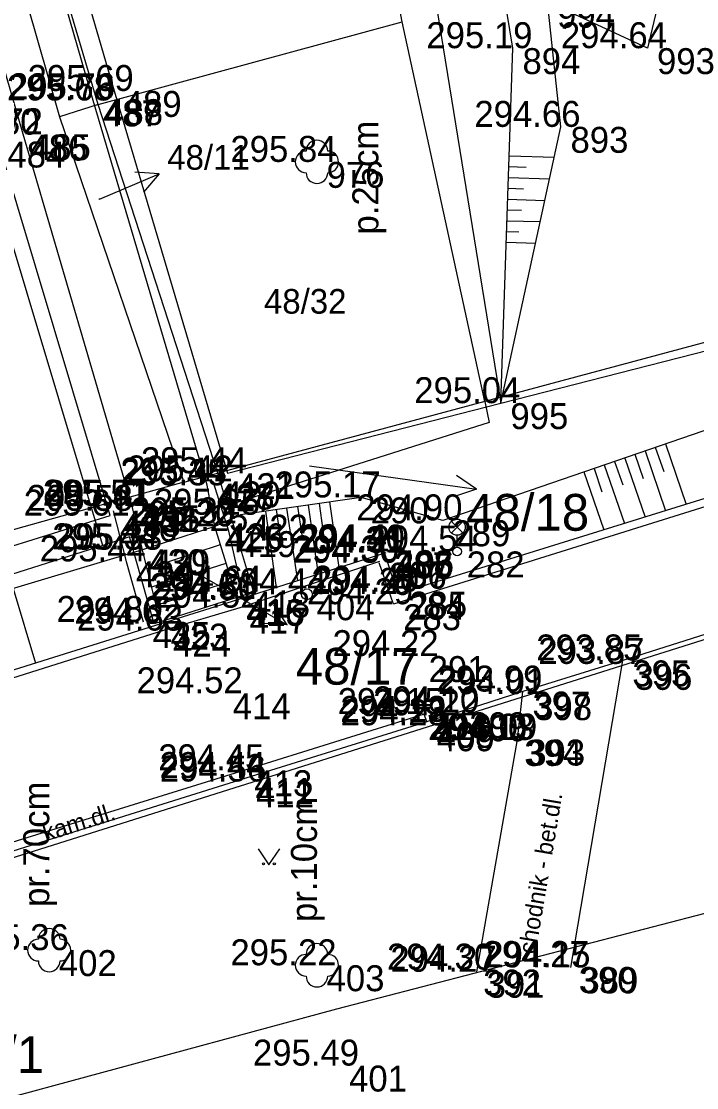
# Model space of a CAD drawing. Extents: x -599970 to -599524, y -1154772 to -1154457.
# Drawn here: x -599781.27 to -599765.66, y -1154687.91 to -1154663.25 of the extents above; entities that cross this region are included whole.
import ezdxf

# ---------------------------------------------------------------- set-up
doc = ezdxf.new("R2010")
doc.units = 0
for name, color, linetype in [('Z-ELEKTRICKE SKRINE LAMPY', 7, 'Continuous'), ('Z-KATASTRALNI MAPA', 7, 'Continuous'), ('Z-PLOT DRATENY', 7, 'Continuous'), ('Z-PLOT DREVENY', 7, 'Continuous'), ('Z-PLYNOVODNI SOUPATA HUP', 7, 'Continuous'), ('Z-PODROBNE BODY', 7, 'Continuous'), ('Z-PODROBNE BODY-CISLO', 7, 'Continuous'), ('Z-PODROBNE BODY-VYSKA', 7, 'Continuous'), ('Z-POPISY OBJEKTU A ZPEVNENYCH PLOCH', 7, 'Continuous'), ('Z-PRUMERY KMENU STROMU', 7, 'Continuous'), ('Z-SCHODY', 7, 'Continuous'), ('Z-SRAFOVANI SVAHU', 7, 'Continuous'), ('Z-STROMY ZNACKY KULTUR', 7, 'Continuous'), ('Z-TERENNI HRANY PATY', 7, 'Continuous'), ('Z-ZABRADLI', 7, 'Continuous'), ('Z-ZPEVNENE PLOCHY', 7, 'Continuous')]:
    doc.layers.add(name, color=color, linetype=linetype)

msp = doc.modelspace()

# ---------------------------------------------------------------- linework, layer by layer
at = {"layer": 'Z-ELEKTRICKE SKRINE LAMPY'}
for p, q in [((-599771.332, -1154675.079), (-599771.068, -1154674.815)), ((-599771.064, -1154675.078), (-599771.328, -1154674.813)), ((-599771.2, -1154675.41), (-599771.2, -1154675.135))]:
    msp.add_line(p, q, dxfattribs=at)
for centre, radius in [((-599771.2, -1154674.948), 0.188), ((-599771.2, -1154675.51), 0.1)]:
    msp.add_circle(centre, radius, dxfattribs=at)
at = {"layer": 'Z-KATASTRALNI MAPA'}
for p, q in [((-599772.47, -1154663.26), (-599776.02, -1154644.14)), ((-599779.5, -1154665.17), (-599784.88, -1154646.97)), ((-599725.18, -1154659.85), (-599770.56, -1154672.04)), ((-599779.5, -1154665.17), (-599772.47, -1154663.26)), ((-599770.56, -1154672.04), (-599772.47, -1154663.26)), ((-599779.5, -1154665.17), (-599780.39, -1154665.46)), ((-599776.73, -1154673.7), (-599779.5, -1154665.17)), ((-599780.39, -1154665.46), (-599777.52, -1154673.91)), ((-599779.47, -1154667.36), (-599778.089, -1154666.774)), ((-599778.089, -1154666.774), (-599778.647, -1154666.739)), ((-599778.089, -1154666.774), (-599778.452, -1154667.2)), ((-599779.47, -1154667.36), (-599779.48, -1154667.36)), ((-599770.56, -1154672.04), (-599776.73, -1154673.7)), ((-599777.52, -1154673.91), (-599776.73, -1154673.7)), ((-599776.51, -1154674.45), (-599776.73, -1154673.7)), ((-599774.61, -1154673.53), (-599772.24, -1154673.86)), ((-599777.52, -1154673.91), (-599779.65, -1154674.5)), ((-599772.24, -1154673.86), (-599770.754, -1154674.069)), ((-599770.754, -1154674.069), (-599771.215, -1154673.751)), ((-599770.754, -1154674.069), (-599771.285, -1154674.247)), ((-599779.39, -1154675.37), (-599779.65, -1154674.5)), ((-599779.39, -1154675.37), (-599848.12, -1154697.2)), ((-599777.73, -1154675.72), (-599776.43, -1154676.46)), ((-599776.43, -1154676.46), (-599775.13, -1154677.21)), ((-599775.13, -1154677.21), (-599775.439, -1154676.743)), ((-599775.13, -1154677.21), (-599775.689, -1154677.177))]:
    msp.add_line(p, q, dxfattribs=at)
for points in [[(-599779.65, -1154674.5), (-599784.9, -1154657), (-599786.85, -1154655.89), (-599787.57, -1154653.53), (-599785.79, -1154652.94), (-599792.35, -1154631.92), (-599798.2, -1154633.66), (-599805.39, -1154642.63)], [(-599784.88, -1154646.97), (-599785.65, -1154647.16), (-599780.39, -1154665.46)], [(-599834.98, -1154699.48), (-599751.66, -1154673.18), (-599740.79, -1154669.9), (-599738.46, -1154669.48), (-599735.86, -1154669.61), (-599733.7, -1154670.53), (-599731.62, -1154671.85), (-599729.9, -1154673.34)], [(-599770.56, -1154672.04), (-599770.46, -1154672.53), (-599776.51, -1154674.45)], [(-599776.51, -1154674.45), (-599775.91, -1154676.45), (-599778.2, -1154677.18), (-599778.77, -1154675.17), (-599779.39, -1154675.37)], [(-599779.65, -1154674.5), (-599852.06, -1154694.84), (-599855.48, -1154695.93)], [(-599783.66, -1154688.71), (-599773.98, -1154686.09), (-599748.46, -1154679.46)]]:
    msp.add_lwpolyline(points, dxfattribs=at)
at = {"layer": 'Z-PLOT DRATENY'}
for points in [[(-599780.14, -1154619.26), (-599779.06, -1154624.05), (-599777.14, -1154634.68), (-599775.65, -1154643.75), (-599773.83, -1154653.48), (-599771.85, -1154661.81), (-599770.19, -1154672.08)], [(-599790.59, -1154625.68), (-599789.41, -1154629.89), (-599785.15, -1154644.86), (-599782.34, -1154653.87), (-599779.13, -1154664.86), (-599776.51, -1154673.7), (-599770.19, -1154672.08), (-599762.65, -1154670.15), (-599753.18, -1154667.49), (-599743.82, -1154665.08), (-599731.66, -1154661.71), (-599725.96, -1154660.31)]]:
    msp.add_lwpolyline(points, dxfattribs=at)
at = {"layer": 'Z-PLOT DREVENY'}
for points in [[(-599779.22, -1154674.68), (-599781.82, -1154666.03), (-599784.68, -1154656.11), (-599785.66, -1154655.83), (-599787.35, -1154656.31)], [(-599812.56, -1154685.16), (-599801.32, -1154681.65), (-599791.39, -1154678.5), (-599786.35, -1154676.9), (-599779.22, -1154674.68)]]:
    msp.add_lwpolyline(points, dxfattribs=at)
at = {"layer": 'Z-PLYNOVODNI SOUPATA HUP'}
msp.add_circle((-599774.67, -1154676.5), 0.125, dxfattribs=at)
at = {"layer": 'Z-PODROBNE BODY'}
for p, q in [((-599769.91, -1154663.87), (-599769.91, -1154663.87)), ((-599766.8, -1154663.87), (-599766.8, -1154663.87)), ((-599779.61, -1154665.08), (-599779.61, -1154665.08)), ((-599779.56, -1154665.05), (-599779.56, -1154665.05)), ((-599779.13, -1154664.86), (-599779.13, -1154664.86)), ((-599768.8, -1154665.69), (-599768.8, -1154665.69)), ((-599781.23, -1154665.86), (-599781.23, -1154665.86)), ((-599774.44, -1154666.5), (-599774.44, -1154666.5)), ((-599770.19, -1154672.08), (-599770.19, -1154672.08)), ((-599776.51, -1154673.7), (-599776.51, -1154673.7)), ((-599776.98, -1154673.94), (-599776.98, -1154673.94)), ((-599776.84, -1154673.89), (-599776.84, -1154673.89)), ((-599776.98, -1154673.98), (-599776.98, -1154673.98)), ((-599778.78, -1154674.45), (-599778.78, -1154674.45)), ((-599778.71, -1154674.46), (-599778.71, -1154674.46)), ((-599773.42, -1154674.26), (-599773.42, -1154674.26)), ((-599779.22, -1154674.68), (-599779.22, -1154674.68)), ((-599779.15, -1154674.57), (-599779.15, -1154674.57)), ((-599776.21, -1154674.66), (-599776.21, -1154674.66)), ((-599776.8, -1154674.93), (-599776.8, -1154674.93)), ((-599776.74, -1154674.86), (-599776.74, -1154674.86)), ((-599771.53, -1154674.79), (-599771.53, -1154674.79)), ((-599776.48, -1154675.04), (-599776.48, -1154675.04)), ((-599778.56, -1154675.46), (-599778.56, -1154675.46)), ((-599778.47, -1154675.47), (-599778.47, -1154675.47)), ((-599772.88, -1154675.53), (-599772.88, -1154675.53)), ((-599772.86, -1154675.49), (-599772.86, -1154675.49)), ((-599772.85, -1154675.54), (-599772.85, -1154675.54)), ((-599772.83, -1154675.48), (-599772.83, -1154675.48)), ((-599771.2, -1154675.51), (-599771.2, -1154675.51)), ((-599778.85, -1154675.74), (-599778.85, -1154675.74)), ((-599773, -1154675.77), (-599773, -1154675.77)), ((-599772.99, -1154675.74), (-599772.99, -1154675.74)), ((-599776.16, -1154676.44), (-599776.16, -1154676.44)), ((-599772.53, -1154676.44), (-599772.53, -1154676.44)), ((-599776.3, -1154676.61), (-599776.3, -1154676.61)), ((-599776.28, -1154676.63), (-599776.28, -1154676.63)), ((-599774.67, -1154676.5), (-599774.67, -1154676.5)), ((-599772.57, -1154676.49), (-599772.57, -1154676.49)), ((-599776.22, -1154676.81), (-599776.22, -1154676.81)), ((-599772.67, -1154676.73), (-599772.67, -1154676.73)), ((-599778.46, -1154677.14), (-599778.46, -1154677.14)), ((-599778.05, -1154677.18), (-599778.05, -1154677.18)), ((-599777.99, -1154677.34), (-599777.99, -1154677.34)), ((-599772.08, -1154677.93), (-599772.08, -1154677.93)), ((-599767.37, -1154678.03), (-599767.37, -1154678.03)), ((-599767.32, -1154678.11), (-599767.32, -1154678.11)), ((-599776.61, -1154678.79), (-599776.61, -1154678.79)), ((-599769.68, -1154678.75), (-599769.68, -1154678.75)), ((-599769.64, -1154678.81), (-599769.64, -1154678.81)), ((-599771.96, -1154679.27), (-599771.96, -1154679.27)), ((-599771.14, -1154679.23), (-599771.14, -1154679.23)), ((-599771.14, -1154679.3), (-599771.14, -1154679.3)), ((-599771.9, -1154679.45), (-599771.9, -1154679.45)), ((-599771.89, -1154679.53), (-599771.89, -1154679.53)), ((-599769.87, -1154679.87), (-599769.87, -1154679.87)), ((-599769.8, -1154679.86), (-599769.8, -1154679.86)), ((-599776.11, -1154680.57), (-599776.11, -1154680.57)), ((-599776.08, -1154680.75), (-599776.08, -1154680.75)), ((-599776.07, -1154680.83), (-599776.07, -1154680.83)), ((-599780.63, -1154684.73), (-599780.63, -1154684.73)), ((-599774.44, -1154685.08), (-599774.44, -1154685.08)), ((-599770.82, -1154685.18), (-599770.82, -1154685.18)), ((-599770.74, -1154685.23), (-599770.74, -1154685.23)), ((-599768.61, -1154685.12), (-599768.61, -1154685.12)), ((-599768.57, -1154685.13), (-599768.57, -1154685.13)), ((-599773.92, -1154687.4), (-599773.92, -1154687.4))]:
    msp.add_line(p, q, dxfattribs=at)
at = {"layer": 'Z-SCHODY'}
for points in [[(-599776.28, -1154676.63), (-599776.8, -1154674.93), (-599778.47, -1154675.47)], [(-599778.36, -1154675.9), (-599776.67, -1154675.35)], [(-599778.05, -1154677.18), (-599778.47, -1154675.47)], [(-599778.26, -1154676.33), (-599776.54, -1154675.78)], [(-599778.15, -1154676.75), (-599776.41, -1154676.19)]]:
    msp.add_lwpolyline(points, dxfattribs=at)
at = {"layer": 'Z-SRAFOVANI SVAHU'}
for points in [[(-599769.99, -1154666.36), (-599768.95, -1154666.39)], [(-599770, -1154666.61), (-599769.6, -1154666.62)], [(-599770.01, -1154666.86), (-599769.06, -1154666.89)], [(-599770.02, -1154667.11), (-599769.66, -1154667.12)], [(-599770.03, -1154667.36), (-599769.17, -1154667.39)], [(-599770.04, -1154667.61), (-599769.71, -1154667.62)], [(-599770.05, -1154667.86), (-599769.28, -1154667.88)], [(-599770.05, -1154668.11), (-599769.77, -1154668.12)], [(-599770.06, -1154668.36), (-599769.38, -1154668.38)], [(-599766.85, -1154673.18), (-599766.38, -1154674.57)], [(-599766.62, -1154673.1), (-599766.42, -1154673.66)], [(-599766.38, -1154673.02), (-599765.9, -1154674.42)], [(-599767.56, -1154673.43), (-599767.37, -1154673.97)], [(-599767.32, -1154673.35), (-599766.85, -1154674.72)], [(-599767.09, -1154673.26), (-599766.9, -1154673.82)], [(-599768.27, -1154673.67), (-599767.81, -1154675.01)], [(-599768.03, -1154673.59), (-599767.85, -1154674.13)], [(-599767.8, -1154673.51), (-599767.33, -1154674.86)], [(-599774.64, -1154674.44), (-599774.41, -1154676.04)], [(-599774.39, -1154674.4), (-599774.3, -1154675.02)], [(-599774.15, -1154674.36), (-599773.93, -1154675.88)], [(-599775.63, -1154674.58), (-599775.38, -1154676.34)], [(-599775.38, -1154674.54), (-599775.28, -1154675.23)], [(-599775.14, -1154674.51), (-599774.89, -1154676.19)], [(-599774.89, -1154674.47), (-599774.79, -1154675.13)], [(-599781.46, -1154676.37), (-599780.95, -1154678.09)]]:
    msp.add_lwpolyline(points, dxfattribs=at)
at = {"layer": 'Z-STROMY ZNACKY KULTUR'}
msp.add_lwpolyline([(-599775.8, -1154682.385), (-599775.55, -1154682.76), (-599775.3, -1154682.385)], dxfattribs=at)
for centre, radius in [((-599774.44, -1154666.5), 0.00025), ((-599775.675, -1154682.735), 0.025), ((-599775.425, -1154682.735), 0.025), ((-599780.63, -1154684.73), 0.00025), ((-599774.44, -1154685.08), 0.00025)]:
    msp.add_circle(centre, radius, dxfattribs=at)
for centre, start, end in [((-599774.44, -1154666.25), 0, 180), ((-599774.69, -1154666.5), 90, 270), ((-599774.19, -1154666.5), 270, 90), ((-599774.44, -1154666.75), 180, 360), ((-599780.63, -1154684.48), 0, 180), ((-599780.88, -1154684.73), 90, 270), ((-599780.38, -1154684.73), 270, 90), ((-599774.44, -1154684.83), 0, 180), ((-599780.63, -1154684.98), 180, 360), ((-599774.69, -1154685.08), 90, 270), ((-599774.19, -1154685.08), 270, 90), ((-599774.44, -1154685.33), 180, 360)]:
    msp.add_arc(centre, 0.25, start, end, dxfattribs=at)
at = {"layer": 'Z-TERENNI HRANY PATY'}
for points in [[(-599770.19, -1154672.08), (-599768.8, -1154665.69), (-599769.11, -1154662.8), (-599769.78, -1154656.63), (-599767.23, -1154647.84), (-599766.21, -1154641.96), (-599766.49, -1154640.37)], [(-599770.19, -1154672.08), (-599769.91, -1154663.87), (-599771.22, -1154655.86), (-599770.65, -1154650.7), (-599770.95, -1154647.47), (-599768.69, -1154645.23)], [(-599742.26, -1154667.02), (-599744.49, -1154666.27), (-599753.03, -1154668.55), (-599762.24, -1154671.6), (-599771.53, -1154674.79), (-599773.42, -1154674.26), (-599776.21, -1154674.66), (-599776.8, -1154674.93)], [(-599778.47, -1154675.47), (-599786.05, -1154677.74), (-599791.05, -1154679.79), (-599801.02, -1154682.6), (-599812.13, -1154686.2)]]:
    msp.add_lwpolyline(points, dxfattribs=at)
at = {"layer": 'Z-ZABRADLI'}
for points in [[(-599776.16, -1154676.44), (-599776.48, -1154675.04), (-599776.84, -1154673.89)], [(-599779.15, -1154674.57), (-599778.85, -1154675.74), (-599778.46, -1154677.14)]]:
    msp.add_lwpolyline(points, dxfattribs=at)
at = {"layer": 'Z-ZPEVNENE PLOCHY'}
for points in [[(-599754.14, -1154621.91), (-599757.46, -1154625.05), (-599757.52, -1154625.29), (-599760.31, -1154636.94), (-599763.2, -1154648.7), (-599766.8, -1154663.87), (-599769.11, -1154662.8), (-599767.23, -1154647.84), (-599764.82, -1154638.47), (-599762.25, -1154627.96), (-599761.65, -1154625.43)], [(-599776.8, -1154674.93), (-599776.98, -1154673.98), (-599779.61, -1154665.08), (-599782.84, -1154653.93), (-599785.44, -1154645), (-599789.78, -1154630.07), (-599790.16, -1154628.81)], [(-599778.47, -1154675.47), (-599778.71, -1154674.46), (-599781.23, -1154665.86), (-599784.02, -1154656.22), (-599785.76, -1154654.87)], [(-599742.28, -1154666.02), (-599742.26, -1154667.02), (-599752.5, -1154670.22), (-599761.75, -1154673.13), (-599772.57, -1154676.49), (-599772.88, -1154675.53)], [(-599742.12, -1154666.17), (-599742.05, -1154667.12), (-599752.44, -1154670.39), (-599761.7, -1154673.3), (-599772.67, -1154676.73), (-599773, -1154675.77)], [(-599741.96, -1154670.11), (-599744.27, -1154670.81), (-599744.9, -1154671.03), (-599746.24, -1154671.41), (-599751.27, -1154672.97), (-599751.54, -1154673.05), (-599760.81, -1154675.95), (-599767.37, -1154678.03), (-599769.68, -1154678.75), (-599771.16, -1154679.23), (-599771.94, -1154679.46)], [(-599772.85, -1154675.54), (-599776.28, -1154676.63), (-599778.05, -1154677.18), (-599785.5, -1154679.52), (-599790.53, -1154681.1), (-599800.67, -1154684.32), (-599811.53, -1154687.77)], [(-599772.99, -1154675.74), (-599776.22, -1154676.81), (-599777.99, -1154677.34), (-599785.42, -1154679.68), (-599790.47, -1154681.24), (-599800.61, -1154684.48), (-599811.46, -1154687.9)], [(-599768.57, -1154685.13), (-599767.37, -1154678.03)], [(-599770.74, -1154685.23), (-599769.8, -1154679.86), (-599769.68, -1154678.75)], [(-599771.9, -1154679.45), (-599771.96, -1154679.27), (-599776.11, -1154680.57), (-599782.94, -1154682.69), (-599783.93, -1154682.97), (-599785.28, -1154683.4), (-599786.24, -1154683.72), (-599788.16, -1154684.29), (-599788.07, -1154684.53)], [(-599771.9, -1154679.45), (-599776.08, -1154680.75), (-599782.88, -1154682.88), (-599783.87, -1154683.12), (-599785.23, -1154683.58), (-599786.18, -1154683.89), (-599788.07, -1154684.53), (-599789.03, -1154684.79), (-599799.87, -1154688.27), (-599810.12, -1154691.54)]]:
    msp.add_lwpolyline(points, dxfattribs=at)

# ---------------------------------------------------------------- texts
at = {"layer": 'Z-KATASTRALNI MAPA'}
for s, height, p in [('48/11', 0.57, (-599777.9, -1154666.68)), ('48/32', 0.57, (-599775.664, -1154670.01)), ('48/18', 0.85, (-599770.99, -1154675.03)), ('48/17', 0.85, (-599774.93, -1154678.59)), ('37/1', 0.85, (-599782.96, -1154687.57))]:
    msp.add_text(s, height=height, dxfattribs=at).set_placement(p)
at = {"layer": 'Z-PODROBNE BODY-CISLO'}
for s, p in [(' 994', (-599769.11, -1154663.4)), (' 894', (-599769.91, -1154664.47)), (' 993', (-599766.8, -1154664.47)), (' 487', (-599779.61, -1154665.68)), (' 488', (-599779.56, -1154665.65)), (' 489', (-599779.13, -1154665.46)), (' 893', (-599768.8, -1154666.29)), (' 484', (-599781.82, -1154666.63)), (' 486', (-599781.31, -1154666.47)), (' 485', (-599781.23, -1154666.46)), (' 976', (-599774.44, -1154667.1)), (' 995', (-599770.19, -1154672.68)), (' 421', (-599776.51, -1154674.3)), (' 428', (-599776.98, -1154674.54)), (' 427', (-599776.98, -1154674.58)), (' 420', (-599776.84, -1154674.49)), (' 432', (-599778.78, -1154675.05)), (' 431', (-599778.71, -1154675.06)), (' 290', (-599773.42, -1154674.86)), (' 436', (-599779.22, -1154675.28)), (' 433', (-599779.15, -1154675.17)), (' 422', (-599776.21, -1154675.26)), (' 425', (-599776.8, -1154675.53)), (' 426', (-599776.74, -1154675.46)), (' 289', (-599771.53, -1154675.39)), (' 419', (-599776.48, -1154675.64)), (' 430', (-599778.56, -1154676.06)), (' 429', (-599778.47, -1154676.07)), (' 287', (-599772.88, -1154676.13)), (' 405', (-599772.85, -1154676.14)), (' 288', (-599772.86, -1154676.09)), (' 406', (-599772.83, -1154676.08)), (' 282', (-599771.2, -1154676.11)), (' 434', (-599778.85, -1154676.34)), (' 407', (-599772.99, -1154676.34)), (' 286', (-599773, -1154676.37)), (' 418', (-599776.16, -1154677.04)), (' 285', (-599772.53, -1154677.04)), (' 416', (-599776.3, -1154677.21)), (' 415', (-599776.28, -1154677.23)), (' 404', (-599774.67, -1154677.1)), (' 284', (-599772.57, -1154677.09)), (' 417', (-599776.22, -1154677.41)), (' 283', (-599772.67, -1154677.33)), (' 435', (-599778.46, -1154677.74)), (' 423', (-599778.05, -1154677.78)), (' 424', (-599777.99, -1154677.94)), (' 291', (-599772.08, -1154678.53)), (' 395', (-599767.37, -1154678.63)), (' 396', (-599767.32, -1154678.71)), (' 414', (-599776.61, -1154679.39)), (' 397', (-599769.68, -1154679.35)), (' 398', (-599769.64, -1154679.41)), (' 410', (-599771.96, -1154679.87)), (' 400', (-599771.14, -1154679.9)), (' 399', (-599771.14, -1154679.83)), (' 408', (-599771.9, -1154680.05)), (' 409', (-599771.89, -1154680.13)), (' 394', (-599769.87, -1154680.47)), (' 393', (-599769.8, -1154680.46)), (' 413', (-599776.11, -1154681.17)), (' 411', (-599776.08, -1154681.35)), (' 412', (-599776.07, -1154681.43)), (' 402', (-599780.63, -1154685.33)), (' 403', (-599774.44, -1154685.68)), (' 392', (-599770.82, -1154685.78)), (' 391', (-599770.74, -1154685.83)), (' 390', (-599768.61, -1154685.72)), (' 389', (-599768.57, -1154685.73)), (' 401', (-599773.92, -1154688))]:
    msp.add_text(s, height=0.6, dxfattribs=at).set_placement(p)
at = {"layer": 'Z-PODROBNE BODY-VYSKA'}
for s, p in [('295.19 ', (-599771.91, -1154663.87)), ('294.64 ', (-599768.8, -1154663.87)), ('295.69 ', (-599781.13, -1154664.86)), ('295.68 ', (-599781.61, -1154665.08)), ('295.76 ', (-599781.56, -1154665.05)), ('294.66 ', (-599770.8, -1154665.69)), ('295.80 ', (-599783.31, -1154665.87)), ('295.72 ', (-599783.23, -1154665.86)), ('295.84 ', (-599776.44, -1154666.5)), ('295.04 ', (-599772.19, -1154672.08)), ('295.44 ', (-599778.51, -1154673.7)), ('295.44 ', (-599778.98, -1154673.94)), ('295.35 ', (-599778.98, -1154673.98)), ('295.42 ', (-599778.84, -1154673.89)), ('295.17 ', (-599775.42, -1154674.26)), ('295.58 ', (-599781.15, -1154674.57)), ('295.51 ', (-599780.78, -1154674.45)), ('295.41 ', (-599780.71, -1154674.46)), ('295.61 ', (-599781.22, -1154674.68)), ('295.25 ', (-599778.21, -1154674.66)), ('294.90 ', (-599773.53, -1154674.79)), ('295.20 ', (-599778.8, -1154674.93)), ('295.32 ', (-599778.74, -1154674.86)), ('295.25 ', (-599778.48, -1154675.04)), ('295.44 ', (-599780.56, -1154675.46)), ('295.33 ', (-599780.47, -1154675.47)), ('294.31 ', (-599774.88, -1154675.53)), ('294.40 ', (-599774.86, -1154675.49)), ('294.31 ', (-599774.85, -1154675.54)), ('294.41 ', (-599774.83, -1154675.48)), ('294.54 ', (-599773.2, -1154675.51)), ('295.44 ', (-599780.85, -1154675.74)), ('294.30 ', (-599775, -1154675.77)), ('294.30 ', (-599774.99, -1154675.74)), ('294.64 ', (-599778.16, -1154676.44)), ('294.44 ', (-599776.67, -1154676.5)), ('294.27 ', (-599774.57, -1154676.49)), ('294.40 ', (-599774.53, -1154676.44)), ('294.61 ', (-599778.3, -1154676.61)), ('294.50 ', (-599778.28, -1154676.63)), ('294.29 ', (-599774.67, -1154676.73)), ('294.52 ', (-599778.22, -1154676.81)), ('294.80 ', (-599780.46, -1154677.14)), ('294.62 ', (-599780.05, -1154677.18)), ('294.63 ', (-599779.99, -1154677.34)), ('294.22 ', (-599774.08, -1154677.93)), ('293.85 ', (-599769.37, -1154678.03)), ('293.87 ', (-599769.32, -1154678.11)), ('293.99 ', (-599771.68, -1154678.75)), ('294.52 ', (-599778.61, -1154678.79)), ('294.01 ', (-599771.64, -1154678.81)), ('294.10 ', (-599773.14, -1154679.23)), ('294.15 ', (-599773.96, -1154679.27)), ('294.13 ', (-599773.9, -1154679.45)), ('294.22 ', (-599773.14, -1154679.3)), ('294.28 ', (-599773.89, -1154679.53)), ('294.13 ', (-599771.87, -1154679.87)), ('294.09 ', (-599771.8, -1154679.86)), ('294.45 ', (-599778.11, -1154680.57)), ('294.44 ', (-599778.08, -1154680.75)), ('294.56 ', (-599778.07, -1154680.83)), ('295.36 ', (-599782.63, -1154684.73)), ('295.22 ', (-599776.44, -1154685.08)), ('294.30 ', (-599772.82, -1154685.18)), ('294.27 ', (-599770.61, -1154685.12)), ('294.15 ', (-599770.57, -1154685.13)), ('294.27 ', (-599772.74, -1154685.23)), ('295.49 ', (-599775.92, -1154687.4))]:
    msp.add_text(s, height=0.6, dxfattribs=at).set_placement(p)
at = {"layer": 'Z-POPISY OBJEKTU A ZPEVNENYCH PLOCH'}
for s, rotation, p in [('kam.dl.', 17.3924, (-599780.71, -1154682.22)), ('chodnik - bet.dl.', 80.4069, (-599769.39, -1154684.84))]:
    msp.add_text(s, height=0.4, rotation=rotation, dxfattribs=at).set_placement(p)
at = {"layer": 'Z-PRUMERY KMENU STROMU'}
for s, p in [('p.25cm', (-599773.02, -1154668.18)), ('pr.70cm', (-599780.63, -1154683.73)), ('pr.10cm', (-599774.44, -1154684.08))]:
    msp.add_text(s, height=0.6, rotation=90, dxfattribs=at).set_placement(p)

doc.saveas('drawing.dxf')
